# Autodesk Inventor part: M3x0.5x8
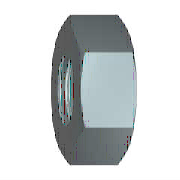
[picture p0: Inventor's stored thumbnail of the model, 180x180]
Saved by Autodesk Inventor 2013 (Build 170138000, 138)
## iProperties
Created: 2009-02
Part Number: M3x0.5x8
Material: 강, 연강
Description: 6각 너트 및 6각 가는 너트
Document SubType Name: Modeling
Standard: KS B 1012
Designer: KYOUNG IL JANG
Standards Organization: KS
Language: ko-KR
Size Designation: C M8
Categories: <MemberInstance><Categories><Category DisplayName="조임쇠" InternalName="e4da775c-781d-43d5-af7c-5136215cf5a6" Mnemonic="FSTN"><Category DisplayName="너트" InternalN
Density: 7.86 g/cm^3
Vendor: CBT Solutions
Mass: 6.84944 g
Surface Area: 7.1883 cm^2
Volume: 0.87143 cm^3
Company: 한국ATC센터
IsCustomPart: 0
Author: KYOUNG IL JANG
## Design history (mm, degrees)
sketch "스케치1"
  geometry: L1 (-7.506, 0)-(-3.753, 6.5); L2 (-3.753, 6.5)-(3.753, 6.5); L3 (3.753, 6.5)-(7.506, 0); L4 (7.506, 0)-(3.753, -6.5); L5 (3.753, -6.5)-(-3.753, -6.5); L6 (-3.753, -6.5)-(-7.506, 0); 2 further points
  constraints: 12 end point, 1 coincident, 1 horizontal, 11 other
  dimensions: "d0" = 15.01111 distance of L3.end L1.start (= 1.1547 x SW)
extrude "본체" new body sketch "스케치1" distance "d1" = 7.9 (= KOH); taper "d2" = 0 deg
sketch "스케치2"
  geometry: L1 (0, 3.753)-(0, 7.506) reference; L2 (0, 7.506)-(7.9, 7.506) reference; L3 (7.9, 3.753)-(7.9, 7.506) reference; L4 (-1.58, 0)-(9.48, 0) reference; L5 (0.581, 7.506)-(0, 6.5); L6 (7.319, 7.506)-(7.9, 6.5)
  constraints: 4 end point, 4 point on line
  dimensions: "d3" = 30 deg angle of L1 L5 (= ANG1); "d4" = 30 deg angle of L3 L6 (= ANG2); "d5" = 13 diameter of L5.end L4 (= SW0); "d6" = 13 diameter of L6.end L4 (= SW01)
revolve "모따기1" sketch "스케치2" stored, may be unused: angle "d7" = 90 deg
sketch "스케치3"
  geometry: A1 r 6.5 centre (0, 0) between (-3.25, -5.629) and (3.25, -5.629) reference; 1 further point
  constraints: 1 coincident
hole "스레드" sketch "스케치3" at (0, 0) diameter "d25" = 6.647; stored, may be unused: countersink angle "d29" = 82 deg, drill point angle "d31" = 118 deg; dims "d26" = 6, "d27" = 4, "d28" = 2, "d30" = 8
workaxis "Work Axis1"
workplane "Work Plane1"
body "Solid1"
chamfer "모따기2" distance "d8" = 0.67658 (= -0.5 x GD1 + 0.5 x NND); stored, may be unused: angle "d9" = 30 deg, second distance "d40" = 0.67658 (= -0.5 x GD1 + 0.5 x NND)
chamfer "모따기3" distance "d10" = 0.67658 (= -0.5 x GD1 + 0.5 x NND); stored, may be unused: angle "d11" = 30 deg, second distance "d41" = 0.67658 (= -0.5 x GD1 + 0.5 x NND)
other parameters: "ANG1" = 30 deg [user parameter; used in 1 equation term], "ANG2" = 30 deg [user parameter; used in 1 equation term], "NND" = 8 [user parameter; used in 4 equation terms], "KOH" = 7.9 [user parameter; used in 1 equation term], "SW" = 13 [user parameter; used in 4 equation terms], "SW0" = 13 (= SW) [user parameter; used in 1 equation term], "SW01" = 13 (= SW) [user parameter; used in 1 equation term], "GD1" = 6.64684 (computed from THREADDIA, PTC, TOA) [user parameter; used in 4 equation terms], "d13" = 0, "d14" = 0, "d39" = 0, "d42" = 0, "GUL" = 0.67658 (= 0.541266 x PTC) [user parameter], "TPU" = 8 (computed from PTC) [user parameter], "THREADDIA" = 8 [user parameter; used in 1 equation term], "TOA" = 30 deg [user parameter; used in 1 equation term], "PTC" = 1.25 [user parameter; used in 4 equation terms], "E0" = 15.015 (= 1.155 x SW) [user parameter], "GAL" = 0.67658 (= 0.541266 x PTC) [user parameter]
